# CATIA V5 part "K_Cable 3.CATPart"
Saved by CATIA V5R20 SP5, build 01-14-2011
Part number: Cable 3
Bounding box of the stored display mesh (mm): x -800 to 800, y -25 to 25, z -25 to 25
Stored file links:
  G:\Khaled_CFAO_2011\SIL\SIL_GR1\gperrin\Khaled\CAD_CATIA\Khaled\K_Cable 3.CATPart
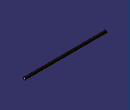
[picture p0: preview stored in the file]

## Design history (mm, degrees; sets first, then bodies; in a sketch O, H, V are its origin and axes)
Body1 (main body)
  Sketch1 on yz-plane, origin (0, 0, 0), H (0, 1, 0), V (0, 0, 1)
    circle A1 centre (0, 0) radius 25
    radius A1 = 25
  Pad1: profile Sketch1, direction (1, 0, 0), length 800, mirrored extent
